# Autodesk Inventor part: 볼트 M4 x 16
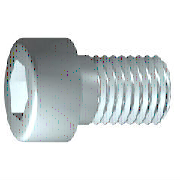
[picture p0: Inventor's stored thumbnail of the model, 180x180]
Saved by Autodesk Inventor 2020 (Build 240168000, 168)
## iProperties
IsCustomPart: 0
Created: 2012-02
Part Number: 볼트 M4 x 16
Material: 스테인리스강
Description: 6각 소켓 머리 캡 나사
Document SubType Name: Modeling
Standard: ISO 4762
Designer: mduedu
Standard Revision: Fourth edition 2004-03-01
Standards Organization: ISO
Language: ko-KR
Size Designation: M4 x 16
Categories: <MemberInstance><Categories><Category DisplayName="조임쇠" InternalName="e4da775c-781d-43d5-af7c-5136215cf5a6" Mnemonic="FSTN"><Category DisplayName="볼트" InternalN
Density: 8.08 g/cm^3
Mass: 2.70334 g
Surface Area: 3.81118 cm^2
Volume: 0.334572 cm^3
Appearance: 반광택
Author: mduedu
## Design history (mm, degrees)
sketch "스케치1"
  geometry: L1 (-1, 0)-(16, 0); L2 (16, 0)-(16, 2); L3 (16, 2)-(1.75, 2); L4 (1.75, 2)-(1.32, 2); L5 (1.32, 2)-(0, 2); L6 (0, 2)-(0, 3.5); L7 (0, 3.5)-(-4, 3.5); L8 (-4, 3.5)-(-4, 1.732); L9 (-4, 1.732)-(-2, 1.732); L10 (-2, 1.732)-(-1, 0); L11 (-8, 0)-(20, 0) reference; L12 (0, -0.7)-(0, 4.2) reference; L13 (1.75, 2)-(0, 2)
  constraints: 22 end point, 6 parallel, 2 collinear, 2 perpendicular, 1 horizontal, 1 point on line
  dimensions: "d1" = 14.25 distance from line of L3.end L2 (= GEL); "d2" = 0.42952 distance of L4.end L3.end (computed from GAL); "d3" = 4 distance between parallel lines of L8 L6 (= KOH); "d4" = 2 distance of L8.end L9.end (= INTI); "d5" = 60 deg angle of L10 L1; "d6" = 4 diameter of L3 L1 (= GD); "d7" = 4 diameter of L5 L1 (= BDM); "d8" = 3.4641 diameter of L9 L1 (= 1.1547 x SW); "d9" = 7 diameter of L7 L1 (= KOD); "d26" = 16 distance between parallel lines of L12 L2 (= NLG)
revolve "본체" sketch "스케치1" stored, may be unused: angle "d10" = 90 deg
sketch "스케치2"
  geometry: L1 (0, -4.9)-(0, 4.9) reference; L2 (-4.9, 0)-(4.9, 0) reference; L3 (1.732, 0)-(0.866, -1.5); L4 (0.866, -1.5)-(-0.866, -1.5); L5 (-0.866, -1.5)-(-1.732, 0); L6 (-1.732, 0)-(-0.866, 1.5); L7 (-0.866, 1.5)-(0.866, 1.5); L8 (0.866, 1.5)-(1.732, 0); 2 further points
  constraints: 12 end point, 1 coincident, 1 horizontal alignment, 1 point on line, 12 other
extrude "슬롯" join sketch "스케치2" stored distance "d11" = 10; taper "d12" = 0 deg
workplane "Work Plane1"
fillet "Fillet2" dims "d30" = 0.1 (= R)
body "Solid1"
fillet "모깎기1" dims "d17" = 0.4 (= RR)
feature "스레드" dims "d13" = 14.25 (= GEL), "d14" = 0
chamfer "모따기1" distance "d15" = 0.42941 (= -0.5 x SPD + 0.5 x GD); stored, may be unused: second distance "d16" = 0.42941 (= GUL), angle "d27" = 45 deg
other parameters: "GD" = 4 [user parameter; used in 2 equation terms], "NLG" = 16 [user parameter; used in 1 equation term], "GEL" = 14.25 [user parameter; used in 2 equation terms], "KOD" = 7 [user parameter; used in 1 equation term], "KOH" = 4 [user parameter; used in 1 equation term], "INTI" = 2 [user parameter; used in 1 equation term], "GAL" = 0.42941 (= 0.61345 x PTC) [user parameter; used in 1 equation term], "GUL" = 0.42941 (= 0.61345 x PTC) [user parameter; used in 1 equation term], "BDM" = 4 (= NND) [user parameter; used in 1 equation term], "SW" = 3 [user parameter; used in 2 equation terms], "RR" = 0.4 [user parameter; used in 1 equation term], "SPD" = 3.14117 (= NND - 1.2269 x PTC) [user parameter; used in 1 equation term], "d19" = 0, "d28" = 0, "d29" = 0, "R" = 0.1 [user parameter; used in 1 equation term], "TOA" = 30 deg [user parameter], "GD1" = 3.14117 (= THREADDIA - 1.2269 x PTC) [user parameter], "THREADDIA" = 4 [user parameter; used in 1 equation term], "FAWI" = 45 deg [user parameter], "TPU" = 14.28571 (computed from PTC) [user parameter], "PTC" = 0.7 [user parameter; used in 5 equation terms], "NND" = 4 [user parameter; used in 2 equation terms], "E0" = 3.465 (= 1.155 x SW) [user parameter]
